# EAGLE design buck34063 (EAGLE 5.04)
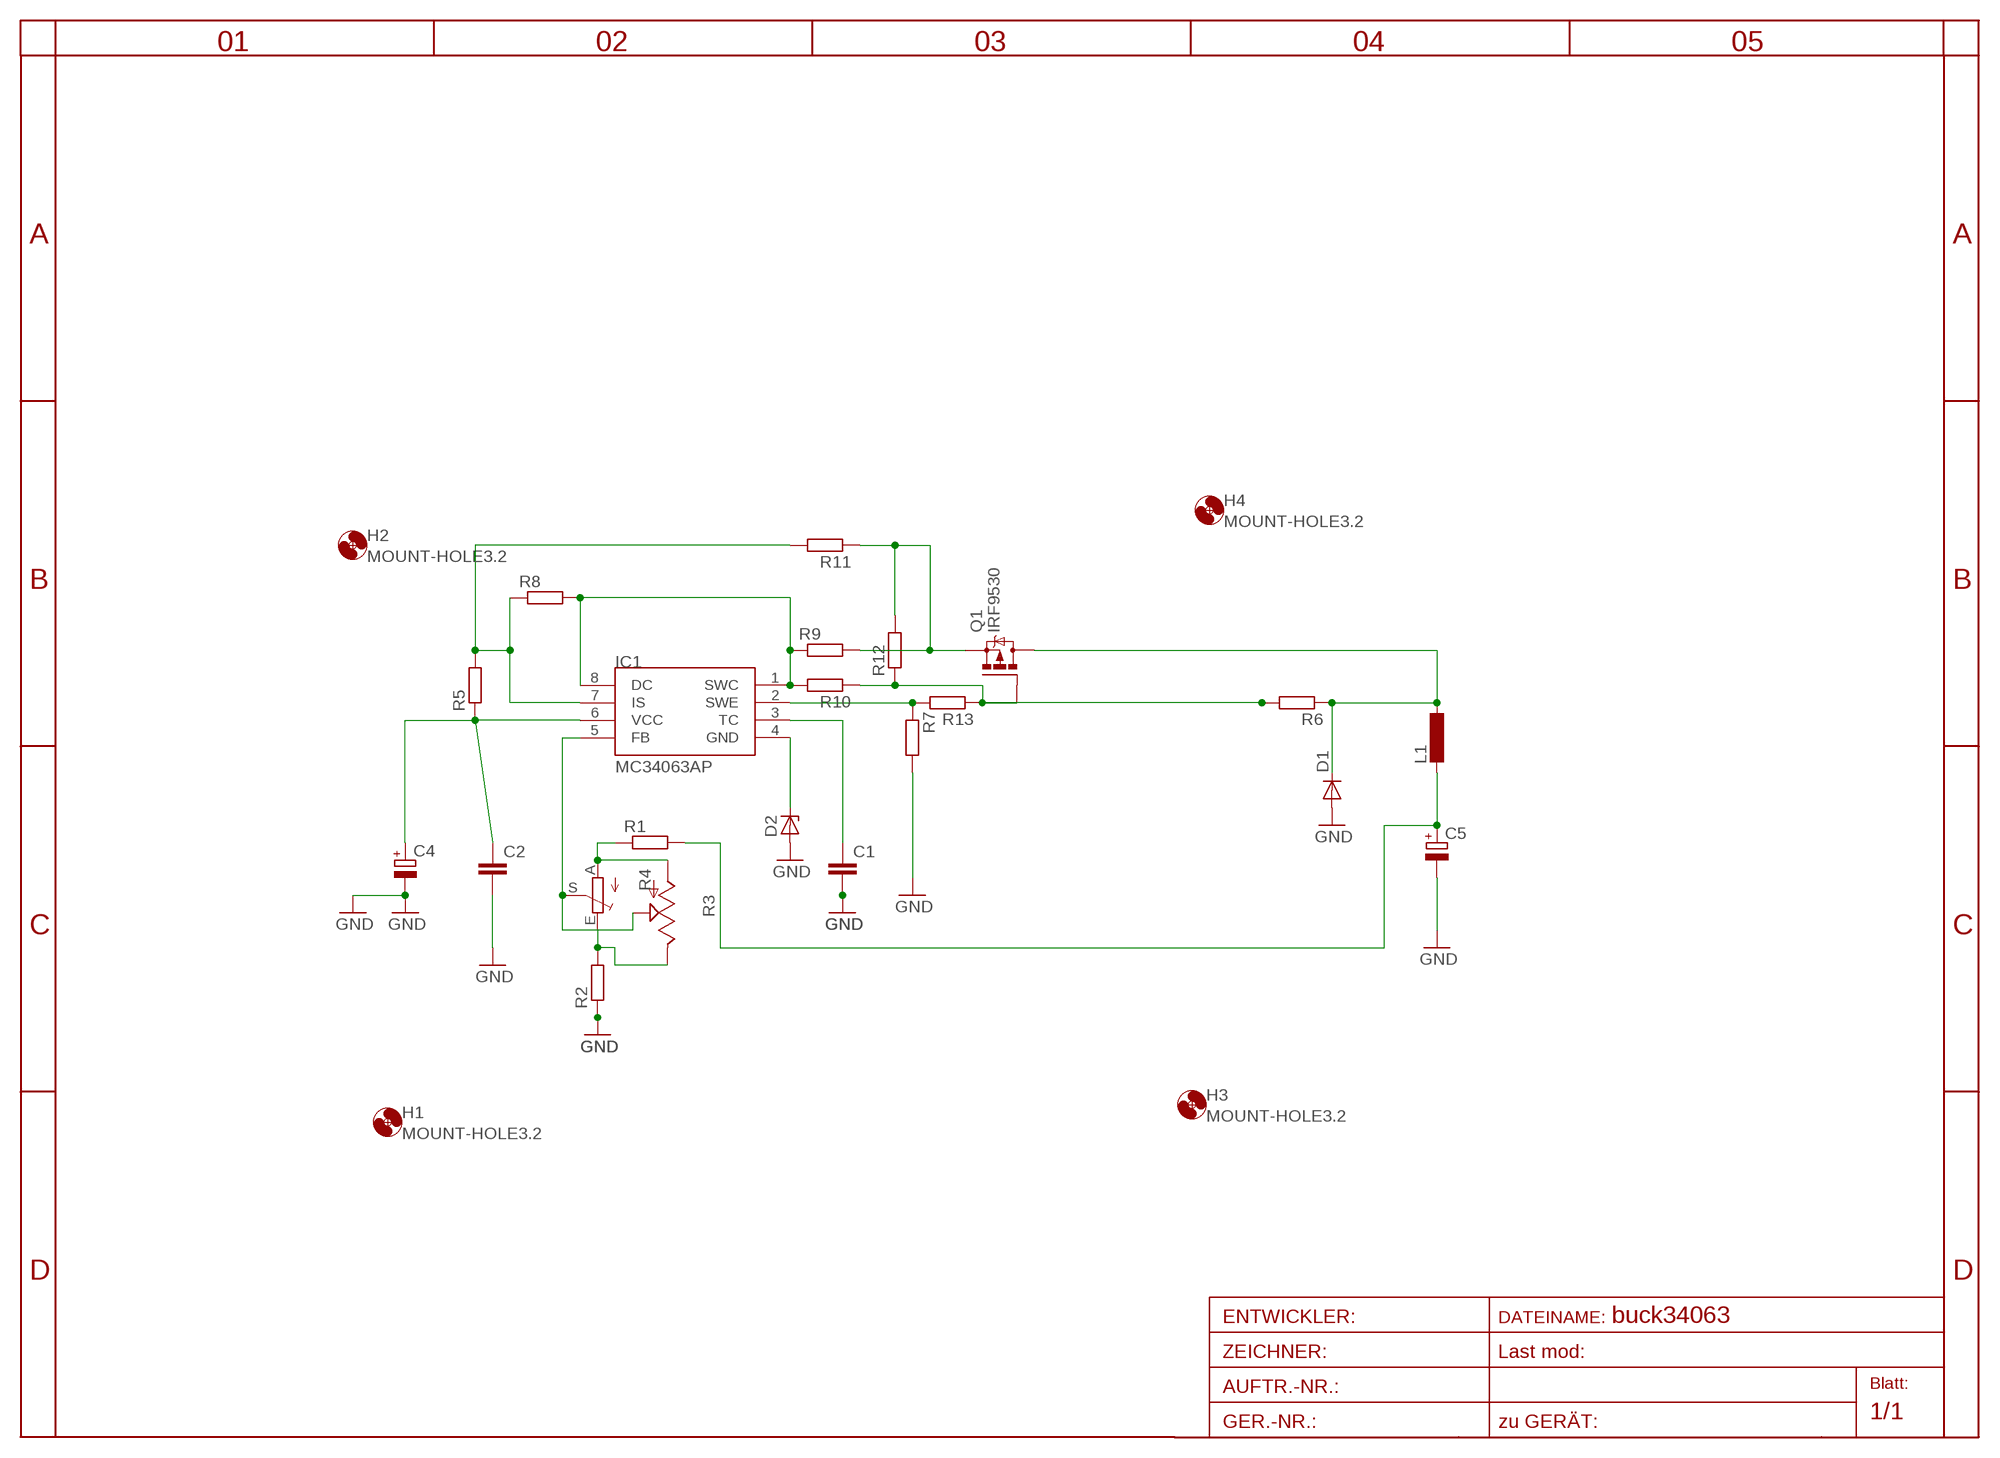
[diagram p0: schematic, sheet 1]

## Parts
C1  C-EU025_050-055X075  [C025_050-055X075]
C2  C-EU025_050-055X075  [C025_050-055X075]
C4  CPOL-EUE5-10.5  [E5-10,5]
C5  CPOL-EUE5-10.5  [E5-10,5]
D1  DIODE-D-10  [D-10]
D2  ZENER-DIODEZD-10  [ZDIO-10]
H1  MOUNT-HOLE3.2  [3,2]
H2  MOUNT-HOLE3.2  [3,2]
H3  MOUNT-HOLE3.2  [3,2]
H4  MOUNT-HOLE3.2  [3,2]
IC1  MC34063AP  [DIL08]
L1  L-EU0207/10  [0207/10]
Q1  IRF9530  [TO220BV]
R1  R-EU_0207/10  [0207/10]
R2  R-EU_0207/10  [0207/10]
R3  TRIM_US-CA6V  [CA6V]
R4  TRIM_EU-CA9V  [CA9V]
R5  R-EU_0207/10  [0207/10]
R6  R-EU_R0603  [R0603]
R7  R-EU_R0603  [R0603]
R8  R-EU_R0603  [R0603]
R9  R-EU_R0603  [R0603]
R10  R-EU_0204/7  [0204/7]
R11  R-EU_0207/10  [0207/10]
R12  R-EU_0207/10  [0207/10]
R13  R-EU_R0603  [R0603]

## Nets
GND: C1.2 C2.2 C4.- C5.- D1.A D2.A R2.1 R7.2
N$1: R1.1 R3.A R4.A
N$2: Q1.G R6.2 R10.1 R12.1 R13.1
N$3: IC1.7(IS) R5.2 R8.1 R11.2
N$4: C1.1 IC1.3(TC)
N$5: D1.C L1.1 Q1.D R6.1
N$6: D2.C IC1.4(GND)
N$7: IC1.5(FB) R3.S R4.S
N$8: R2.2 R3.E R4.E
N$9: IC1.1(SWC) IC1.8(DC) R8.2 R9.1 R10.2
N$11: IC1.2(SWE) R7.1 R13.2
PCHS: Q1.S R9.2 R11.1 R12.2
VCC: C2.1 C4.+ IC1.6(VCC) R5.1
VOUT: C5.+ L1.2 R1.2

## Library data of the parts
C1 C2 = rcl:C-EU: CAPACITOR, European symbol
C4 C5 = rcl:CPOL-EU: POLARIZED CAPACITOR, European symbol
D1 = diode:DIODE-: DIODE
D2 = diode:ZENER-DIODE: Z-Diode
H1-H4 = holes:MOUNT-HOLE: MOUNTING HOLE with drill center marker
IC1 = mc34063:MC34063
L1 = rcl:L-EU: INDUCTOR, European symbol
Q1 = transistor-power:IRF9530: P-CHANNEL HEXFET POWER-MOS-FET Source: http://www.irf.com/product-info/datasheets/data/irf9530.pdf
R1 R2 R5-R13 = rcl:R-EU_: RESISTOR, European symbol
R3 = pot:TRIM_US-: POTENTIOMETER
R4 = pot:TRIM_EU-: POTENTIOMETER

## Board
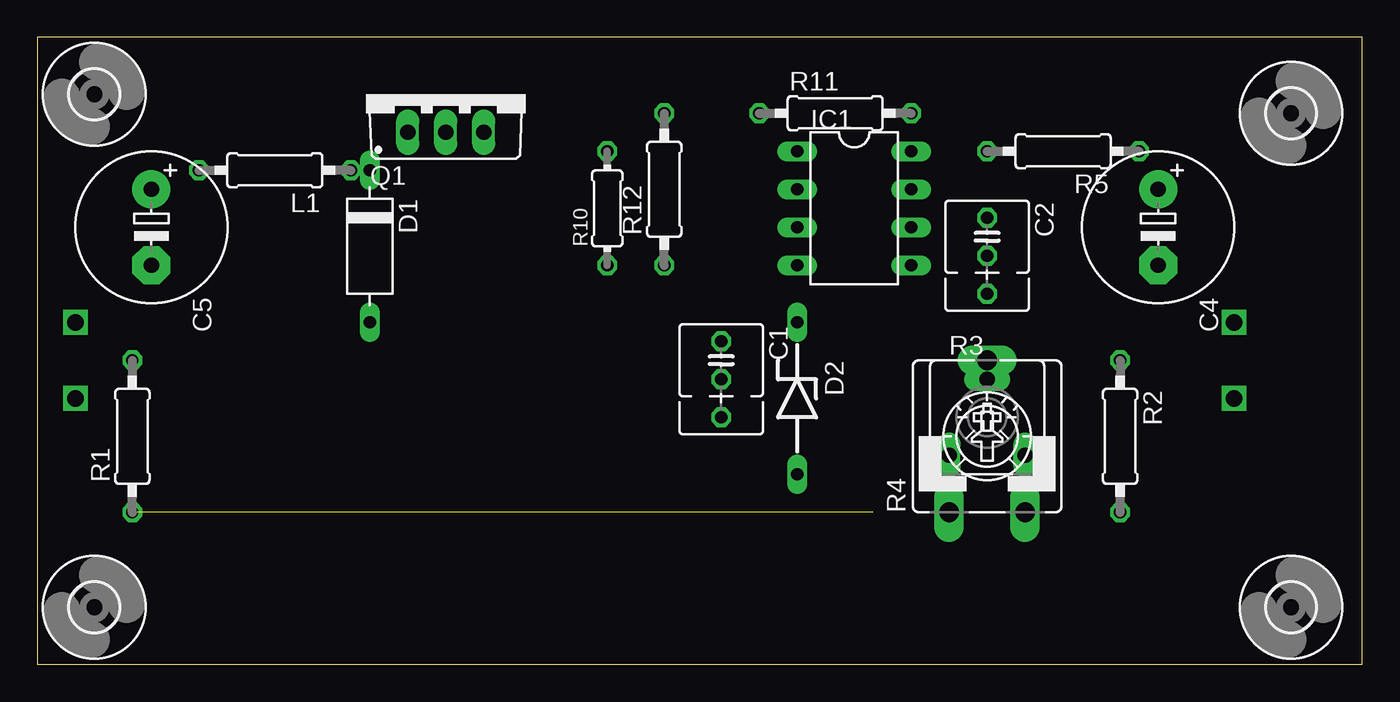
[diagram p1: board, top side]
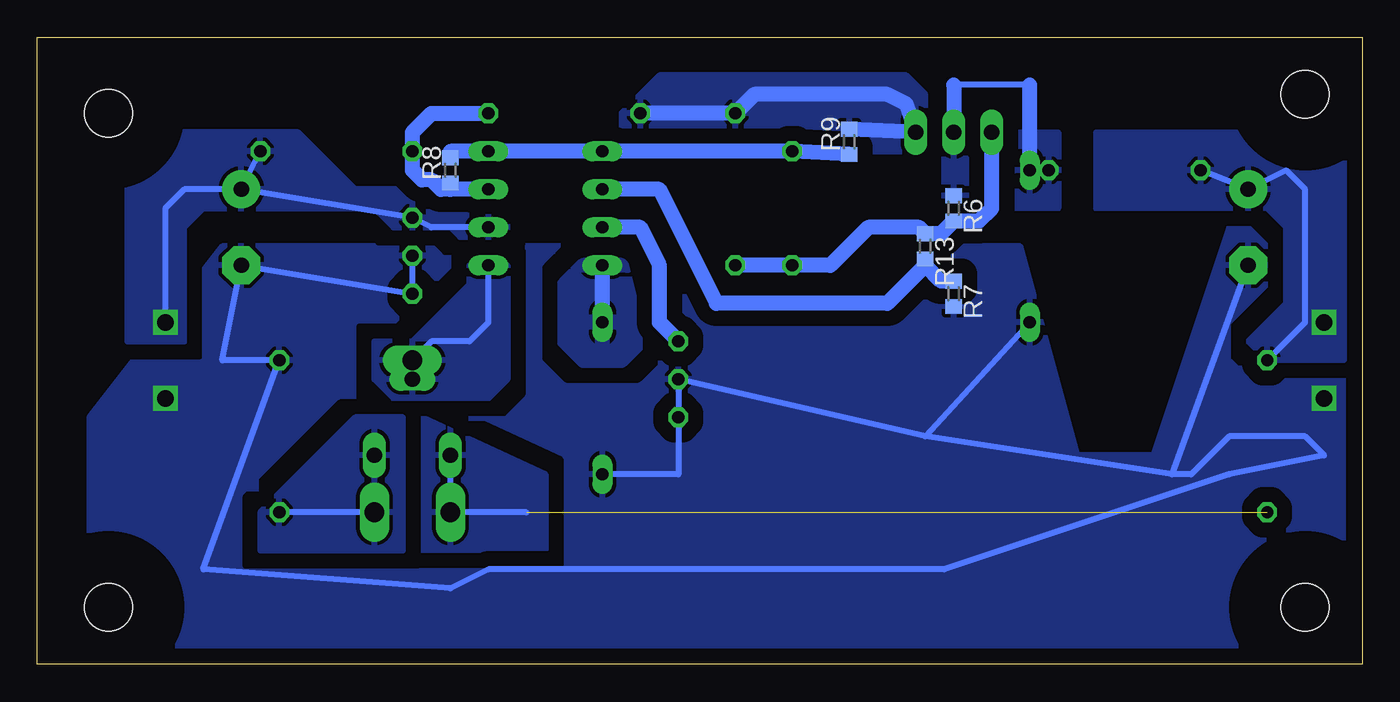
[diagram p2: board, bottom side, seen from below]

Size 88.57 x 41.9 mm. Coordinates in mm from the lower left corner, seen from the top.
Outline: 0,0 88.57,0 88.57,41.9 0,41.9 0,0
Copper layers (1*16): Top 0.035mm / dielectric 1.5mm / Bottom 0.035mm
Design rules "default": minimum track width 10mil, minimum drill 24mil, track to track 8mil, track to pad 8mil, pad to pad 8mil, via to via 8mil, smd to smd 8mil, copper to edge 40mil, drill to drill 8mil, minimum pad ring 10mil, minimum via ring 8mil, stop-mask expansion 4mil, vias tented up to drill 0mil, thermal gap 10mil

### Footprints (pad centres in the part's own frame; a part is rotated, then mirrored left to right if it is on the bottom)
C025_050-055X075 = drill 0.813 octagon: 1 -1.27,0; 2 1.27,0; 3 3.81,0
E5-10,5 = drill 1.016 pad 2.54 round: + -2.54,0 | drill 1.016 pad 2.54 octagon: - 2.54,0
D-10 = drill 0.813 long: A 5.08,0; C -5.08,0
ZDIO-10 = drill 0.813 long: A 5.08,0; C -5.08,0
3,2 = hole 3.2: 0,0
DIL08 = drill 0.813 long: 1 -3.81,-3.81; 2 -1.27,-3.81; 3 1.27,-3.81; 4 3.81,-3.81; 5 3.81,3.81; 6 1.27,3.81; 7 -1.27,3.81; 8 -3.81,3.81
0207/10 = drill 0.813 octagon: 1 -5.08,0; 2 5.08,0
TO220BV = drill 1.016 long: D 0,-2.54; G -2.54,-2.54; S 2.54,-2.54
CA6V = drill 1.016 long: A -2.54,-2.54; E 2.54,-2.54; S 0,2.54
CA9V = drill 1.321 long: A -2.54,-5.08; E 2.54,-5.08; S 0,5.08
R0603 = smd 1 x 1.1: 1 -0.85,0; 2 0.85,0
0204/7 = drill 0.813 octagon: 1 -3.81,0; 2 3.81,0

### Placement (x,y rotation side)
C1  45.72,20.32 270 top
C2  63.5,28.57 270 top
C4  74.93,29.21 270 top
C5  7.62,29.21 270 top
D1  22.23,27.94 270 top
D2  50.8,17.78 270 top
H1  83.82,36.83 0 top
H2  83.82,3.81 0 top
H3  3.81,3.81 0 top
H4  3.81,38.1 0 top
IC1  54.61,30.48 270 top
L1  15.88,33.02 180 top
Q1  27.3,38.1 0 top
R1  6.35,15.24 90 top
R2  72.39,15.24 270 top
R3  63.5,16.51 0 top
R4  63.5,15.24 0 top
R5  68.58,34.29 180 top
R6  27.3,30.48 270 bottom
R7  27.3,24.77 270 bottom
R8  60.96,33.02 90 bottom
R9  34.29,34.92 90 bottom
R10  38.1,30.48 90 top
R11  53.34,36.83 0 top
R12  41.91,31.75 90 top
R13  29.21,27.94 270 bottom

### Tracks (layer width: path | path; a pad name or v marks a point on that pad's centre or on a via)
GND  (via drill 1.1)
  Bottom 0.406: 12.7,12.7 C5.- | D2.A 45.72,12.7 C1.2 29.21,15.24 | 12.7,12.7 11.43,12.7 8.89,15.24 3.81,15.24 2.54,13.97 8.89,12.7 27.94,6.35 58.42,6.35 60.96,5.08 77.47,6.35 R2.1 76.2,20.32 C4.- 63.5,24.77 C2.2 | 12.7,12.7 29.21,15.24 | 29.21,15.24 D1.A
  other vias: 80.01,17.78 2.54,17.78
  pour Bottom (isolate 1.016, rank 5): 1.27,2.54 1.27,24.13 6.35,29.21 8.89,29.21 13.97,13.97 19.05,13.97 22.86,27.94 76.2,27.94 85.09,16.51 85.09,1.27 2.54,1.27
N$1  (1 unrouted)
  Bottom 0.406: R3.A R4.A 55.88,10.16
  pour Bottom (isolate 1.016, rank 2): 54.61,12.7 54.61,7.62 62.87,7.62 62.87,16.51
N$2
  Bottom 1.016: R12.1 R10.1 35.56,26.67 33.02,29.21 29.63,29.21 R13.1 28.14,28.79 R6.2 25.61,29.63 24.77,30.48 Q1.G
N$3
  Bottom 1.016: IC1.7 60.96,31.75 | 60.96,31.75 61.59,31.75 62.23,32.38 62.87,32.38 63.5,33.02 R5.2 63.5,35.56 62.23,36.83 R11.2 | 60.96,31.75 R8.1
N$4
  Bottom 1.016: IC1.3 48.26,29.21 46.99,26.67 46.99,22.86 C1.1
N$5
  Bottom 0.406: 22.23,38.73 27.3,38.73
  Bottom 1.016: 27.3,38.73 Q1.D | D1.C 22.23,38.73
  pour Bottom (isolate 1.016, rank 4): 20.32,35.56 20.32,30.48 27.94,30.48 27.94,35.56
N$6
  Bottom 1.016: D2.C IC1.4
  pour Bottom (isolate 1.016, rank 2): 49.53,26.67 52.07,26.67 53.34,25.4 53.34,21.59 52.07,20.32 49.53,20.32 48.26,21.59
N$7
  Bottom 0.406: IC1.5 58.42,22.86 59.69,21.59 62.23,21.59 R4.S R3.S
  pour Bottom (isolate 1.016): 57.15,26.67 57.15,19.05 58.42,17.78 64.77,17.78 66.04,19.05 66.04,21.59 63.5,21.59 59.69,25.4 59.69,26.67
N$8
  Bottom 0.406: R4.E R2.2
  pour Bottom (isolate 1.016): 64.14,16.51 67.31,16.51 73.66,10.16 73.66,7.62 64.14,7.62
N$9
  Bottom 1.016: R9.1 R10.2 IC1.1 IC1.8 60.96,34.29 R8.2
N$11
  Bottom 1.016: IC1.2 46.99,31.75 43.18,24.13 31.75,24.13 29.21,26.67 | R7.1 28.16,25.61 29.21,26.67 | 29.21,26.67 R13.2
PCHS
  Bottom 1.016: R9.2 Q1.S 30.48,37.47 31.75,38.1 40.64,38.1 R12.2 R11.1
  pour Bottom (isolate 1.016, rank 2): 29.21,35.56 29.21,38.1 30.48,39.37 46.99,39.37 49.53,36.83 49.53,35.56 48.26,34.29 30.48,34.29
VCC  (via drill 1.1)
  Bottom 0.406: IC1.6 62.23,29.21 C2.1 C4.+ | C4.+ R5.1 | C4.+ 78.74,31.75 80.01,30.48 v80.01,22.86
  pour Bottom (isolate 1.016, rank 2): 57.15,30.48 62.23,30.48 63.5,31.75 67.31,31.75 71.12,35.56 80.01,35.56 82.55,33.02 82.55,21.59 78.74,21.59 78.74,29.21 77.47,30.48 66.04,30.48 64.77,29.21 60.96,29.21 60.33,28.57 57.15,28.57
VOUT  (via drill 1.1)
  Bottom 0.406: L1.2 C5.+ 5.08,33.02 3.81,31.75 3.81,22.86 R1.2
  other vias: 2.54,22.86
  pour Bottom (isolate 1.016, rank 3): 17.78,35.56 2.54,35.56 0,33.02 0,21.59 1.27,20.32 6.35,20.32 7.62,21.59 5.08,24.13 5.08,29.21 6.35,30.48 17.78,30.48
